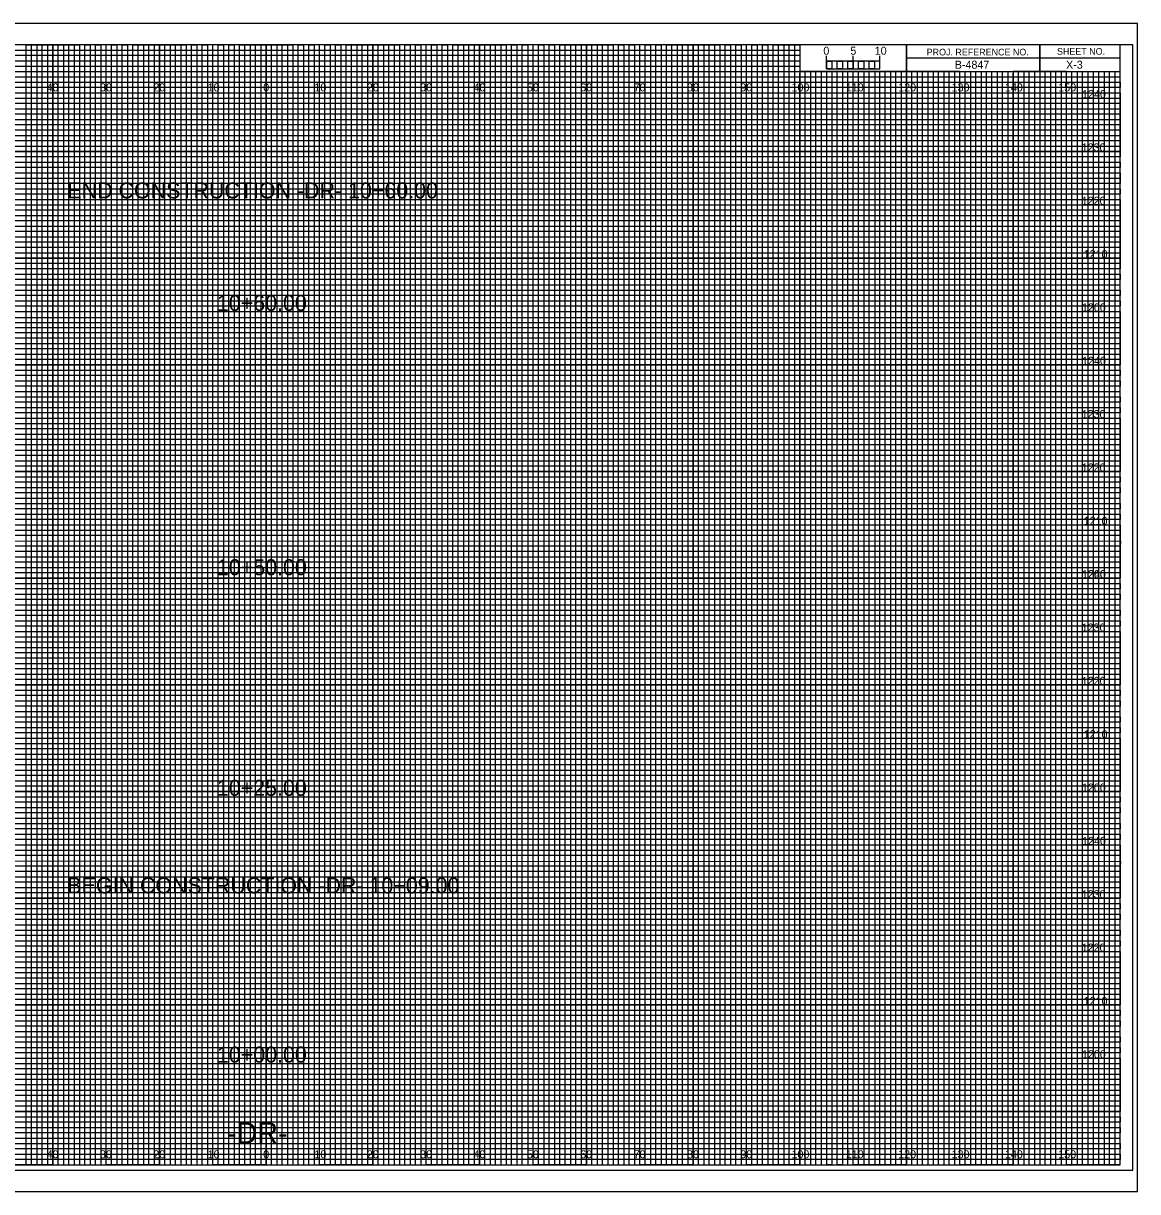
# Model space of a CAD drawing. Extents: x -13 to 323, y -5 to 214.
# Drawn here: x 114.5 to 323.3, y -5 to 214 of the extents above; entities that cross this region are included whole.
import ezdxf

# ---------------------------------------------------------------- set-up
doc = ezdxf.new("R2010")
doc.units = 0
for name, color, linetype in [('Default', 7, 'Continuous'), ('Prop XS Alignment Label', 7, 'Continuous'), ('Prop XS Bar Scale Labels', 7, 'Continuous'), ('Prop XS Elevation Labels', 7, 'Continuous'), ('Prop XS Offset Labels', 7, 'Continuous'), ('Prop XS Project Number', 7, 'Continuous'), ('Prop XS Sheet Number', 7, 'Continuous'), ('Prop XS Station Labels', 7, 'Continuous'), ('Sheet Cross Section CELL', 7, 'Continuous'), ('Sheet Cross Section Grid Major CELL', 7, 'Continuous'), ('Sheet Cross Section Grid Middle CELL', 7, 'Continuous'), ('Sheet Cross Section Grid Minor 1 CELL', 7, 'Continuous'), ('Sheet Cross Section Grid Minor 2 CELL', 7, 'Continuous'), ('Sheet Cross Section Scale CELL', 7, 'Continuous'), ('Sheet Cutting Line CELL', 7, 'Continuous'), ('Sheet DOT Grid CELL', 7, 'Continuous'), ('Sheet Plot Border Inside CELL', 7, 'Continuous'), ('Sheet Plot Border Outside CELL', 7, 'Continuous')]:
    doc.layers.add(name, color=color, linetype=linetype)

msp = doc.modelspace()

# ---------------------------------------------------------------- linework, layer by layer
at = {"layer": 'Sheet Cross Section CELL'}
for p, q in [((305, 210), (305, 205)), ((305, 205), (305, 210)), ((280, 207.5), (280, 205)), ((320, 207.49), (280, 207.49)), ((280, 205), (320, 205))]:
    msp.add_line(p, q, dxfattribs=at)
for points in [[(320, 210), (0, 210), (0, 0), (320, 0)], [(280, 210), (260, 210), (260, 205.03), (280, 205.03)], [(320, 210), (280, 210), (280, 205), (320, 205)]]:
    msp.add_lwpolyline(points, close=True, dxfattribs=at)
at = {"layer": 'Sheet Cross Section Grid Major CELL'}
for p, q in [((130, 210), (120, 210)), ((120, 210), (120, 0)), ((130, 0), (130, 210)), ((150, 210), (140, 210)), ((140, 210), (140, 0)), ((150, 0), (150, 210)), ((170, 210), (160, 210)), ((160, 210), (160, 0)), ((170, 0), (170, 210)), ((190, 210), (180, 210)), ((180, 210), (180, 0)), ((190, 0), (190, 210)), ((210, 210), (200, 210)), ((200, 210), (200, 0)), ((210, 0), (210, 210)), ((230, 210), (220, 210)), ((220, 210), (220, 0)), ((230, 0), (230, 210)), ((250, 210), (240, 210)), ((240, 210), (240, 0)), ((250, 0), (250, 210)), ((260, 210), (260, 0)), ((270, 0), (270, 205)), ((290, 205), (280, 205)), ((280, 205), (280, 0)), ((290, 0), (290, 205)), ((310, 205), (300, 205)), ((300, 205), (300, 0)), ((310, 0), (310, 205)), ((120, 0), (110, 0)), ((140, 0), (130, 0)), ((160, 0), (150, 0)), ((180, 0), (170, 0)), ((200, 0), (190, 0)), ((220, 0), (210, 0)), ((240, 0), (230, 0)), ((260, 0), (250, 0)), ((280, 0), (270, 0)), ((300, 0), (290, 0)), ((320, 0), (310, 0)), ((320, 0), (320, 0))]:
    msp.add_line(p, q, dxfattribs=at)
for points in [[(0, 200), (320, 200), (320, 190), (0, 190)], [(0, 180), (320, 180), (320, 170), (0, 170)], [(0, 160), (320, 160), (320, 150), (0, 150)], [(0, 140), (320, 140), (320, 130), (0, 130)], [(0, 120), (320, 120), (320, 110), (0, 110)], [(0, 100), (320, 100), (320, 90), (0, 90)], [(0, 80), (320, 80), (320, 70), (0, 70)], [(0, 60), (320, 60), (320, 50), (0, 50)], [(0, 40), (320, 40), (320, 30), (0, 30)], [(0, 20), (320, 20), (320, 10), (0, 10)]]:
    msp.add_lwpolyline(points, dxfattribs=at)
at = {"layer": 'Sheet Cross Section Grid Middle CELL'}
for points in [[(105, 0), (115, 0), (115, 210), (125, 210), (125, 0), (135, 0), (135, 210), (145, 210), (145, 0), (155, 0), (155, 210), (165, 210), (165, 0), (175, 0), (175, 210), (185, 210), (185, 0), (195, 0), (195, 210), (205, 210), (205, 0), (215, 0), (215, 210), (225, 210), (225, 0), (235, 0), (235, 210), (245, 210), (245, 0), (255, 0), (255, 210), (259.93, 210), (260, 210), (260, 205), (264.99, 205), (264.99, 0), (275, 0), (275, 205), (285, 205), (285, 0), (295, 0), (295, 205), (305, 205), (305, 0), (315, 0), (315, 205)], [(0, 205), (275, 205)], [(0, 185), (320, 185), (320, 195), (0, 195)], [(0, 165), (320, 165), (320, 175), (0, 175)], [(0, 145), (320, 145), (320, 155), (0, 155)], [(0, 125), (320, 125), (320, 135), (0, 135)], [(0, 105), (320, 105), (320, 115), (0, 115)], [(0, 85), (320, 85), (320, 95), (0, 95)], [(0, 65), (320, 65), (320, 75), (0, 75)], [(0, 45), (320, 45), (320, 55), (0, 55)], [(0, 25), (320, 25), (320, 35), (0, 35)], [(0, 5), (320, 5), (320, 15), (0, 15)]]:
    msp.add_lwpolyline(points, dxfattribs=at)
at = {"layer": 'Sheet Cross Section Grid Minor 1 CELL'}
for p, q in [((0, 209), (260, 209)), ((260, 209), (260, 207.98)), ((260, 207.98), (0, 207.98)), ((0, 207), (260, 207)), ((260, 205.89), (0, 205.89)), ((260, 207), (260, 205.89)), ((0, 204), (320, 204))]:
    msp.add_line(p, q, dxfattribs=at)
for points in [[(0, 203), (270, 203), (320, 203), (320, 202), (0, 202)], [(0, 201), (320, 201), (320, 199), (0, 199)], [(0, 198), (320, 198), (320, 197), (0, 196.98)], [(0, 196), (320, 196), (320, 194), (0, 194)], [(0, 193), (320, 193), (320, 192), (0, 192)], [(0, 191), (320, 191), (320, 189), (0, 189)], [(0, 188), (320, 188), (320, 187), (0, 187)], [(0, 186), (320, 186), (320, 184), (0, 184)], [(0, 183), (320, 183), (320, 182), (0, 182)], [(0, 181), (320, 181), (320, 179), (0, 179)], [(0, 178), (320, 178), (320, 177), (0, 177)], [(0, 176), (320, 176), (320, 173.95), (320, 173), (320, 172), (0, 172)], [(0, 174), (320, 174), (320, 173), (0, 173)], [(0, 171), (320, 171), (320, 169), (0, 169.03)], [(0, 169.03), (320, 169), (320, 168), (0, 168)], [(0, 167), (320, 167), (320, 166), (0, 166)], [(0, 164), (320, 164), (320, 163), (0, 163)], [(0, 162), (320, 162), (320, 161), (0, 161)], [(-0.07, 158.89), (320, 158.89), (320, 157.88), (-0.07, 157.88)], [(0, 157), (320, 157), (320, 156), (0, 156)], [(0, 154), (320, 154), (320, 153), (0, 153)], [(0, 152), (320, 152), (320, 151), (0, 151)], [(0, 149), (320, 149), (320, 148), (0, 148)], [(0, 147), (320, 147), (320, 146), (0, 146)], [(0, 144), (320, 144), (320, 143), (0, 143)], [(0, 142), (320, 142), (320, 141), (0, 141)], [(0, 139), (320, 139), (319.99, 137.98), (0, 138)], [(0, 137), (320, 137), (320, 136), (0, 136)], [(0, 134), (320, 134), (320, 133), (0, 133)], [(0, 132), (320, 132), (320, 131), (0, 131)], [(0, 129), (320, 129), (320, 128), (0, 128)], [(0, 127), (320, 127), (320, 126), (0, 126)], [(0, 124), (320, 124), (320, 123), (0, 123)], [(0, 122), (320, 122), (320, 121), (0, 121)], [(0, 119), (320, 119), (320, 118), (0, 118)], [(0, 116.99), (320.07, 116.91), (320, 116), (0, 116)], [(0, 114), (320, 114), (320, 113), (0, 113)], [(0, 112), (320, 112), (320, 111), (0, 111)], [(0, 109), (320, 109), (320, 108), (0, 108)], [(0, 107), (320, 107), (320, 106), (0, 106)], [(0, 104), (320, 104), (320, 103), (0, 103)], [(0, 102), (320, 102), (320, 101), (0, 101)], [(0, 99), (320, 99), (320, 98), (0, 98)], [(0, 97), (320, 97), (320, 96), (0, 96)], [(0, 94), (320, 94), (320, 93), (0, 93)], [(0, 92), (320, 92), (320, 91), (0, 91)], [(0, 89), (320, 89), (320, 88), (0, 88)], [(0, 87), (320, 87), (320, 86), (0, 86)], [(0, 84), (320, 84), (320, 83), (0, 83)], [(0, 82), (320, 82), (320, 81), (0, 81)], [(0, 79), (320, 79), (319.99, 77.98), (0, 78)], [(0, 77), (320, 77), (320, 76), (0, 76)], [(0, 74), (320, 74), (320, 73), (0, 73)], [(0, 72), (320, 72), (320, 71), (0, 71)], [(0, 69), (320, 69), (320, 68), (0, 68)], [(0, 67), (320, 67), (320, 66), (0, 66)], [(0, 64), (320, 64), (320, 63), (0, 63)], [(0, 62), (320, 62), (320, 61), (0, 61)], [(0, 59), (320, 59), (320, 58), (0, 58)], [(0, 56.99), (320.07, 56.91), (320, 56), (0, 56)], [(0, 54), (320, 54), (320, 53), (0, 53)], [(0, 52), (320, 52), (320, 51), (0, 51)], [(0, 49), (320, 49), (320, 48), (0, 48)], [(0, 47), (320, 47), (320, 46), (0, 46)], [(0, 44), (320, 44), (320, 43), (0, 43)], [(0, 42), (320, 42), (320, 41), (0, 41)], [(0, 39), (320, 39), (320, 38), (0, 38)], [(0, 37), (320, 37), (320, 36), (0, 36)], [(0, 34), (320, 34), (320, 33), (0, 33)], [(0, 32), (320, 32), (320, 31), (0, 31)], [(0, 29), (320, 29), (320, 28), (0, 28)], [(0, 27), (320, 27), (320, 26), (0, 26)], [(0, 24), (320, 24), (320, 23), (0, 23)], [(0, 22), (320, 22), (320, 21), (0, 21)], [(0, 19), (320, 19), (320, 18), (0, 18)], [(0, 17), (320, 17), (320, 16), (0, 16)], [(0, 14), (320, 14), (320, 13), (0, 13)], [(0, 12), (320, 12), (320, 11), (0, 11)], [(0, 9), (320, 9), (320, 8), (0, 8)], [(0, 7), (320, 7), (320, 6), (0, 6)], [(0, 4), (320, 4), (320, 3), (0, 3)], [(0, 2), (320, 2), (320, 1), (0, 1)]]:
    msp.add_lwpolyline(points, dxfattribs=at)
at = {"layer": 'Sheet Cross Section Grid Minor 2 CELL'}
for p, q in [((267, 205), (266.01, 205)), ((266.01, 205), (266.01, 0)), ((267, 0), (267, 205)), ((269, 205), (268, 205)), ((268, 205), (268, 0)), ((269, 0), (269, 205)), ((266.01, 0), (265, 0)), ((268, 0), (267, 0))]:
    msp.add_line(p, q, dxfattribs=at)
for points in [[(115, 0), (116, 0), (116, 210), (117, 210), (117, 0)], [(117, 0), (118, 0), (118, 210), (119, 210), (119, 0)], [(120, 0), (121, 0), (121, 210), (122, 210), (122, 0)], [(122, 0), (123, 0), (123, 210), (124, 210), (124, 0)], [(125, 0), (126, 0), (126, 210), (127, 210), (127, 0)], [(127, 0), (128, 0), (128, 210), (129, 210), (129, 0)], [(130, 0), (131, 0), (131, 210), (132, 210), (132, 0)], [(132, 0), (133, 0), (133, 210), (134, 210), (134, 0)], [(135, 0), (136, 0), (136, 210), (137, 210), (137, 0)], [(137, 0), (138, 0), (138, 210), (139, 210), (139, 0)], [(140, 0), (141, 0), (141, 210), (142, 210), (142, 0)], [(142, 0), (143, 0), (143, 210), (144, 210), (144, 0)], [(145, 0), (146, 0), (146, 210), (147, 210), (147, 0)], [(147, 0), (148, 0), (148, 210), (149, 210), (149, 0)], [(150, 0), (151, 0), (151, 210), (152, 210), (152, 0)], [(152, 0), (153, 0), (153, 210), (154, 210), (154, 0)], [(155, 0), (156, 0), (156, 210), (157, 210), (157, 0)], [(157, 0), (158, 0), (158, 210), (159, 210), (159, 0)], [(160, 0), (161, 0), (161, 210), (162, 210), (162, 0)], [(162, 0), (163, 0), (163, 210), (164, 210), (164, 0)], [(165, 0), (166, 0), (166, 210), (167, 210), (167, 0)], [(167, 0), (168, 0), (168, 210), (169, 210), (169, 0)], [(170, 0), (171, 0), (171, 210), (172, 210), (172, 0)], [(172, 0), (173, 0), (173, 210), (174, 210), (174, 0)], [(175, 0), (176, 0), (176, 210), (177, 210), (177, 0)], [(177, 0), (178, 0), (178, 210), (179, 210), (179, 0)], [(180, 0), (181, 0), (181, 210), (182, 210), (182, 0)], [(182, 0), (183, 0), (183, 210), (184, 210), (184, 0)], [(185, 0), (186, 0), (186, 210), (187, 210), (187, 0)], [(187, 0), (188, 0), (188, 210), (189, 210), (189, 0)], [(190, 0), (191, 0), (191, 210), (192, 210), (192, 0)], [(192, 0), (193, 0), (193, 210), (194, 210), (194, 0)], [(195, 0), (196, 0), (196, 210), (197, 210), (197, 0)], [(197, 0), (198, 0), (198, 210), (199, 210), (199, 0)], [(200, 0), (201, 0), (201, 210), (202, 210), (202, 0)], [(202, 0), (203, 0), (203, 210), (204, 210), (204, 0)], [(205, 0), (206, 0), (206, 210), (207, 210), (207, 0)], [(207, 0), (208, 0), (208, 210), (209, 210), (209, 0)], [(210, 0), (211, 0), (211, 210), (212, 210), (212, 0)], [(212, 0), (213, 0), (213, 210), (214, 210), (214, 0)], [(215, 0), (216, 0), (216, 210), (217, 210), (217, 0)], [(217, 0), (218, 0), (218, 210), (219, 210), (219, 0)], [(220, 0), (221, 0), (221, 210), (222, 210), (222, 0)], [(222, 0), (223, 0), (223, 210), (224, 210), (224, 0)], [(225, 0), (226, 0), (226, 210), (227, 210), (227, 0)], [(227, 0), (228, 0), (228, 210), (229, 210), (229, 0)], [(230, 0), (231, 0), (231, 210), (232, 210), (232, 0)], [(232, 0), (233, 0), (233, 210), (234, 210), (234, 0)], [(235, 0), (236, 0), (236, 210), (237, 210), (237, 0)], [(237, 0), (238, 0), (238, 210), (239, 210), (239, 0)], [(240, 0), (241, 0), (241, 210), (242, 210), (242, 0)], [(242, 0), (243, 0), (243, 210), (244, 210), (244, 0)], [(245, 0), (246, 0), (246, 210), (247, 210), (247, 0)], [(247, 0), (248, 0), (248, 210), (249, 210), (249, 0)], [(250, 0), (251, 0), (251, 210), (252, 210), (252, 0)], [(252, 0), (253, 0), (253, 210), (254, 210), (254, 0)], [(255, 0), (256, 0), (256, 210), (257, 210), (257, 0)], [(257, 0), (258, 0), (258, 210), (259, 210), (259, 0)], [(260, 0), (261, 0), (261, 205), (262.02, 205), (262.02, 0)], [(262, 0), (263, 0), (263, 205), (263.99, 205), (263.99, 0)], [(270, 0), (270.98, 0), (270.98, 205), (272, 205), (272, 0)], [(272, 0), (273, 0), (273, 205), (274.05, 205), (274.05, 0)], [(275, 0), (276, 0), (276, 205), (277, 205), (277, 0)], [(277, 0), (278, 0), (278, 205), (279, 205), (279, 0)], [(280, 0), (281, 0), (281, 205), (282, 205), (282, 0)], [(282, 0), (283, 0), (283, 205), (284, 205), (284, 0)], [(285, 0), (286, 0), (286, 205), (287, 205), (287, 0)], [(287, 0), (288, 0), (288, 205), (289, 205), (289, 0)], [(290, 0), (291, 0), (291, 205), (292, 205), (292, 0)], [(292, 0), (293, 0), (293, 205), (294, 205), (294, 0)], [(295, 0), (296, 0), (296, 205), (297, 205), (297, 0)], [(297, 0), (298, 0), (298, 205), (299, 205), (299, 0)], [(300, 0), (301, 0), (301, 205), (302, 205), (302, 0)], [(302, 0), (303, 0), (303, 205), (304, 205), (304, 0)], [(305, 0), (306, 0), (306, 205), (307, 205), (307, 0)], [(307, 0), (308, 0), (308, 205), (309, 205), (309, 0)], [(310, 0), (311, 0), (311, 205), (312, 205), (312, 0)], [(312, 0), (313, 0), (313, 205), (314, 205), (314, 0)], [(315, 0), (316, 0), (316, 205), (317, 205), (317, 0)], [(317, 0), (318, 0), (318, 205), (319, 205), (319, 0)]]:
    msp.add_lwpolyline(points, dxfattribs=at)
at = {"layer": 'Sheet Cross Section Scale CELL'}
for p, q in [((265, 205.49), (265, 207.9)), ((265, 206.9), (265, 207.9)), ((270, 205.49), (270, 207.9)), ((275, 205.49), (275, 207.9)), ((275, 206.9), (275, 207.9))]:
    msp.add_line(p, q, dxfattribs=at)
for points in [[(275, 206.9), (265, 206.9), (265, 205.49), (275, 205.49)], [(265, 206.9), (266, 206.9), (266, 205.49), (265, 205.49)], [(267, 206.9), (268, 206.9), (268, 205.49), (267, 205.49)], [(269, 206.9), (270, 206.9), (270, 205.49), (269, 205.49)], [(271, 206.9), (272, 206.9), (272, 205.49), (271, 205.49)], [(273, 206.9), (274, 206.9), (274, 205.49), (273, 205.49)]]:
    msp.add_lwpolyline(points, close=True, dxfattribs=at)
at = {"layer": 'Sheet Cutting Line CELL'}
for p, q in [((323.3, 214), (-13.4, 214)), ((-13.4, -5), (323.3, -5))]:
    msp.add_line(p, q, dxfattribs=at)
at = {"layer": 'Sheet DOT Grid CELL'}
for p, q in [((120, 0), (120, 210)), ((130, 0), (130, 210)), ((140, 0), (140, 210)), ((150, 0), (150, 210)), ((160, 0), (160, 210)), ((170, 0), (170, 210)), ((180, 0), (180, 210)), ((190, 0), (190, 210)), ((200, 0), (200, 210)), ((210, 0), (210, 210)), ((220, 0), (220, 210)), ((230, 0), (230, 210)), ((240, 0), (240, 210)), ((250, 0), (250, 210)), ((260, 0), (260, 204.69)), ((270, 0), (270, 204.69)), ((280, 0), (280, 204.69)), ((290, 0), (290, 204.69)), ((300, 0), (300, 204.69)), ((310, 0), (310, 204.69)), ((0, 200), (320, 200)), ((0, 190), (320, 190)), ((0, 180), (320, 180)), ((0, 170), (320, 170)), ((0, 160), (320, 160)), ((0, 150), (320, 150)), ((0, 140), (320, 140)), ((0, 130), (320, 130)), ((0, 120), (320, 120)), ((0, 110), (320, 110)), ((0, 100), (320, 100)), ((0, 90), (320, 90)), ((0, 80), (320, 80)), ((0, 70), (320, 70)), ((0, 60), (320, 60)), ((0, 50), (320, 50)), ((0, 40), (320, 40)), ((0, 30), (320, 30)), ((0, 20), (320, 20)), ((0, 10), (320, 10))]:
    msp.add_line(p, q, dxfattribs=at)
at = {"layer": 'Sheet Plot Border Inside CELL'}
msp.add_lwpolyline([(-10.8, -1), (322.4, -1), (322.4, 210), (-10.8, 210)], close=True, dxfattribs=at)
at = {"layer": 'Sheet Plot Border Outside CELL'}
msp.add_lwpolyline([(-13.4, -5), (323.3, -5), (323.3, 214), (-13.4, 214)], close=True, dxfattribs=at)

# ---------------------------------------------------------------- texts
at = {"layer": 'Default'}
for s, p in [('END CONSTRUCTION -DR- 10+60.00', (122.75, 181.19)), ('BEGIN CONSTRUCTION -DR- 10+09.00', (122.75, 50.9))]:
    msp.add_text(s, height=3, dxfattribs=at).set_placement(p)
at = {"layer": 'Prop XS Alignment Label'}
msp.add_text('-DR-', height=4, dxfattribs=at).set_placement((152.7, 4))
at = {"layer": 'Prop XS Bar Scale Labels'}
for s, p in [('5', (269.47, 208.12)), ('10', (274.04, 208.12))]:
    msp.add_text(s, height=1.5, dxfattribs=at).set_placement(p)
at = {"layer": 'Prop XS Elevation Labels'}
for s, p in [('1240', (312.9, 200)), ('1230', (312.82, 190)), ('1220', (312.83, 180)), ('1210', (313.2, 170)), ('1200', (312.87, 160)), ('1240', (312.9, 150)), ('1230', (312.82, 140)), ('1220', (312.83, 130)), ('1210', (313.2, 120)), ('1200', (312.87, 110)), ('1240', (312.9, 110)), ('1230', (312.82, 100)), ('1220', (312.83, 90)), ('1210', (313.2, 80)), ('1200', (312.87, 70)), ('1240', (312.9, 60)), ('1230', (312.82, 50)), ('1220', (312.83, 40)), ('1210', (313.2, 30)), ('1200', (312.87, 20))]:
    msp.add_text(s, height=1.5, dxfattribs=at).set_placement(p)
at = {"layer": 'Prop XS Offset Labels'}
for s, p in [('40', (118.86, 201.25)), ('30', (128.86, 201.25)), ('20', (138.86, 201.25)), ('10', (149.04, 201.25)), ('0', (159.45, 201.25)), ('0', (159.45, 201.25)), ('10', (169.04, 201.25)), ('20', (178.86, 201.25)), ('30', (188.86, 201.25)), ('40', (198.86, 201.25)), ('50', (208.86, 201.25)), ('60', (218.86, 201.25)), ('70', (228.86, 201.25)), ('80', (238.86, 201.25)), ('90', (248.86, 201.25)), ('100', (258.44, 201.25)), ('110', (268.62, 201.25)), ('120', (278.44, 201.25)), ('130', (288.44, 201.25)), ('140', (298.44, 201.25)), ('150', (308.44, 201.25)), ('40', (118.86, 1.25)), ('30', (128.86, 1.25)), ('20', (138.86, 1.25)), ('10', (149.04, 1.25)), ('0', (159.45, 1.25)), ('0', (159.45, 1.25)), ('10', (169.04, 1.25)), ('20', (178.86, 1.25)), ('30', (188.86, 1.25)), ('40', (198.86, 1.25)), ('50', (208.86, 1.25)), ('60', (218.86, 1.25)), ('70', (228.86, 1.25)), ('80', (238.86, 1.25)), ('90', (248.86, 1.25)), ('100', (258.44, 1.25)), ('110', (268.62, 1.25)), ('120', (278.44, 1.25)), ('130', (288.44, 1.25)), ('140', (298.44, 1.25)), ('150', (308.44, 1.25))]:
    msp.add_text(s, height=1.5, dxfattribs=at).set_placement(p)
at = {"layer": 'Prop XS Project Number'}
msp.add_text('B-4847', height=1.5, dxfattribs=at).set_placement((289.04, 205.5))
at = {"layer": 'Prop XS Sheet Number'}
msp.add_text('X-3', height=1.5, dxfattribs=at).set_placement((309.89, 205.5))
at = {"layer": 'Prop XS Station Labels'}
for s, p in [('10+60.00', (150.77, 160.09)), ('10+50.00', (150.77, 110.55)), ('10+25.00', (150.77, 69.2)), ('10+00.00', (150.77, 19.19))]:
    msp.add_text(s, height=3, dxfattribs=at).set_placement(p)
at = {"layer": 'Sheet Cross Section CELL'}
for s, p in [('PROJ. REFERENCE NO.', (283.77, 207.99)), ('SHEET NO.', (308.19, 208.12))]:
    msp.add_text(s, height=1.25, dxfattribs=at).set_placement(p)
at = {"layer": 'Sheet Cross Section Scale CELL'}
msp.add_text('0', height=1.5, dxfattribs=at).set_placement((264.41, 208.12))

doc.saveas('drawing.dxf')
